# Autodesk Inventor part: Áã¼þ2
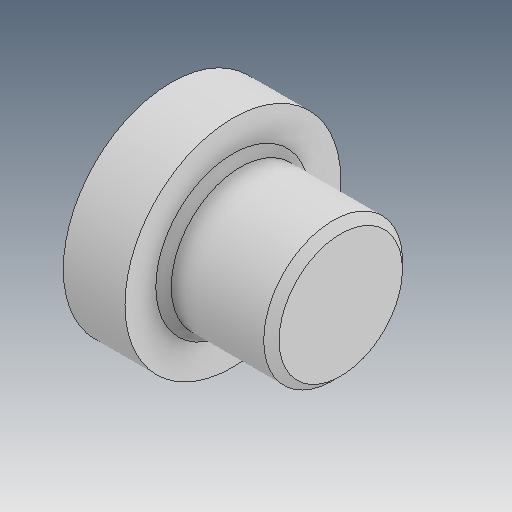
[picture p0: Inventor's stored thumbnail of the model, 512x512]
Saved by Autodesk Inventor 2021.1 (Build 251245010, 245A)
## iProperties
Created: 2019-04
Part Number: Áã¼þ2
Material: Ogólny
Document SubType Name: Modeling
Designer: user
Density: 1 g/cm^3
Appearance: Domyślna
Author: user
Revision Number: ÈÎºÎ
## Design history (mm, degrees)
feature "ÊäÈë1"
node "Bryła1"
